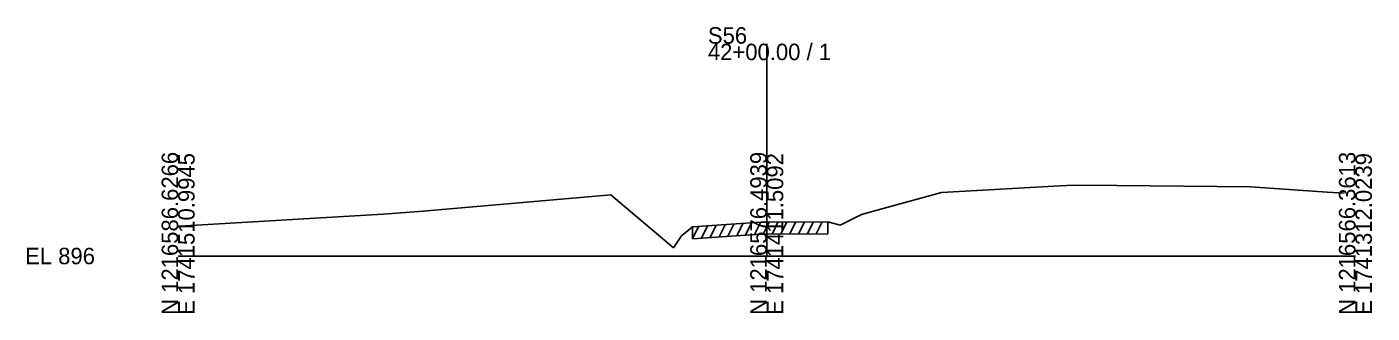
# Model space of a CAD drawing. Extents: x -26 to 1203, y -10 to 19541.
# Drawn here: x -25.7 to 202.8, y 16990.3 to 17038.9 of the extents above; entities that cross this region are included whole.
import ezdxf

# ---------------------------------------------------------------- set-up
doc = ezdxf.new("R2010")
doc.units = 0
for name, color, linetype in [('RD_GPK_XS_Cell', 7, 'Continuous'), ('RD_XS_ExGround', 7, 'Continuous'), ('RD_XS_ExPaveRet', 7, 'Continuous'), ('RD_XS_TX_Elev_EX', 7, 'Continuous')]:
    doc.layers.add(name, color=color, linetype=linetype)

msp = doc.modelspace()

# ---------------------------------------------------------------- linework, layer by layer
at = {"layer": 'RD_GPK_XS_Cell'}
for p, q in [((100, 17000), (100, 17036.06)), ((0, 17000), (100, 17000)), ((100, 17000), (200, 17000))]:
    msp.add_line(p, q, dxfattribs=at)
at = {"layer": 'RD_XS_ExGround'}
msp.add_lwpolyline([(0, 17005.06), (1.19, 17005.15), (34.85, 17007.09), (41.63, 17007.6), (73.51, 17010.37), (74.32, 17009.72), (84.15, 17001.41), (85.52, 17003.45), (87.4, 17004.94), (98.09, 17005.67), (99, 17005.72), (100, 17005.72), (110.37, 17005.78), (112.48, 17005.24), (112.81, 17005.4), (116.12, 17007.05), (119.78, 17008.08), (129.71, 17010.76), (148.77, 17011.88), (152.12, 17012.02), (159.46, 17011.97), (182.2, 17011.77), (195.18, 17010.82), (198.09, 17010.68)], dxfattribs=at)
at = {"layer": 'RD_XS_ExPaveRet'}
for p, q in [((88.9, 17003.04), (89.93, 17005.11)), ((90.4, 17003.14), (91.43, 17005.21)), ((91.9, 17003.25), (92.93, 17005.32)), ((93.4, 17003.35), (94.43, 17005.42)), ((94.9, 17003.45), (95.93, 17005.52)), ((96.4, 17003.55), (97.43, 17005.63)), ((97.9, 17003.66), (98.93, 17005.71)), ((99.4, 17003.72), (100.4, 17005.72)), ((100.9, 17003.73), (101.9, 17005.73)), ((102.4, 17003.74), (103.4, 17005.74)), ((103.9, 17003.74), (104.9, 17005.75)), ((105.4, 17003.75), (106.4, 17005.76)), ((106.9, 17003.76), (107.9, 17005.77)), ((108.4, 17003.77), (109.4, 17005.78)), ((110.37, 17005.78), (110.37, 17003.78)), ((87.4, 17002.94), (88.43, 17005.01)), ((87.4, 17002.94), (87.4, 17004.94)), ((87.4, 17002.94), (98.09, 17003.67)), ((98.09, 17003.67), (99, 17003.72)), ((99, 17003.72), (100, 17003.72)), ((100, 17003.72), (110.37, 17003.78))]:
    msp.add_line(p, q, dxfattribs=at)

# ---------------------------------------------------------------- texts
at = {"layer": 'RD_GPK_XS_Cell'}
for s, p in [('S56', (90, 17036.06)), ('42+00.00 / 1', (90, 17033.26)), ('EL 896', (-26, 16998.6))]:
    msp.add_text(s, height=2.8, dxfattribs=at).set_placement(p)
for s, p in [('N 1216586.6266', (0, 16990)), ('E 1741510.9945', (2.8, 16990)), ('N 1216576.4939', (100, 16990)), ('E 1741411.5092', (102.8, 16990)), ('N 1216566.3613', (200, 16990)), ('E 1741312.0239', (202.8, 16990))]:
    msp.add_text(s, height=2.8, rotation=90, dxfattribs=at).set_placement(p)
at = {"layer": 'RD_XS_TX_Elev_EX'}
msp.add_text('898.86', height=0.1, rotation=90, dxfattribs=at).set_placement((100.1, 17005.72))

doc.saveas('drawing.dxf')
